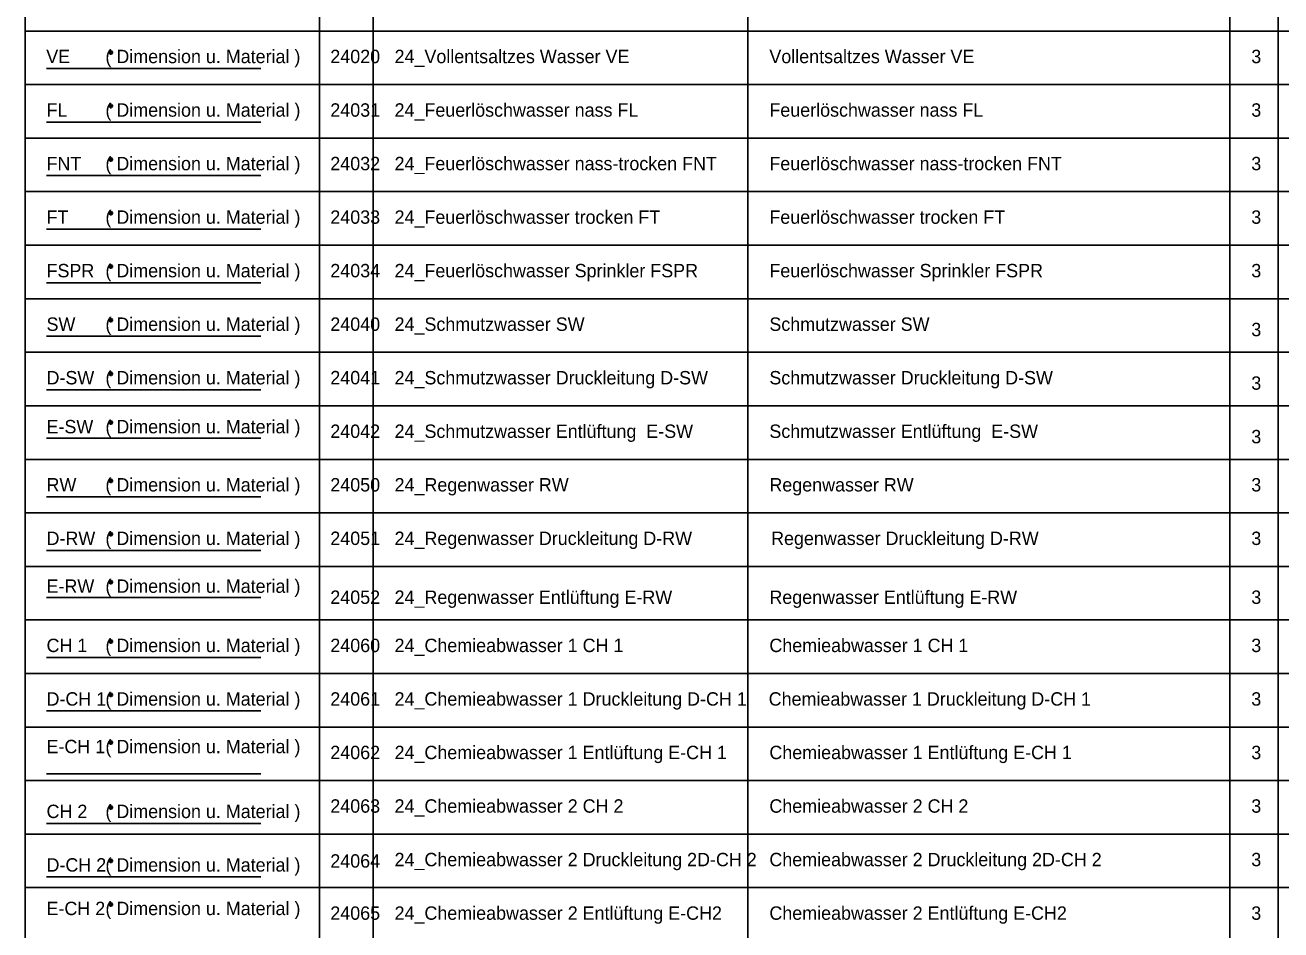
# Model space of a CAD drawing. Extents: x -29 to 48, y -113 to 16.
# Drawn here: x 0 to 23.45, y -30.79 to -13.89 of the extents above; entities that cross this region are included whole.
import ezdxf

# ---------------------------------------------------------------- set-up
doc = ezdxf.new("R2010")
doc.units = 0
for name, color, linetype in [('24_Chemieabwasser 1 CH 1', 7, 'Continuous'), ('24_Chemieabwasser 1 Druckleitung CH 1', 7, 'Continuous'), ('24_Chemieabwasser 1 Entlüftung E-CH 1', 7, 'Continuous'), ('24_Chemieabwasser 2 CH 2', 7, 'Continuous'), ('24_Chemieabwasser 2 Druckleitung CH 2', 7, 'Continuous'), ('24_Chemieabwasser 2 Entlüftung E-CH2', 7, 'Continuous'), ('24_Feuerlöschwasser nass FL', 7, 'Continuous'), ('24_Feuerlöschwasser nass-trocken FNT', 7, 'Continuous'), ('24_Feuerlöschwasser Sprinkler FSPR', 7, 'Continuous'), ('24_Feuerlöschwasser trocken FT', 7, 'Continuous'), ('24_Regenwasser Druckleitung D-RW', 7, 'Continuous'), ('24_Regenwasser Entlüftung E-RW', 7, 'Continuous'), ('24_Regenwasser RW', 7, 'Continuous'), ('24_Schmutzwasser Druckleitung D-SW', 7, 'Continuous'), ('24_Schmutzwasser Entlüftung  E-SW', 7, 'Continuous'), ('24_Schmutzwasser SW', 7, 'Continuous'), ('24_Vollentsaltzes Wasser VE', 7, 'Continuous'), ('Default', 7, 'Continuous')]:
    doc.layers.add(name, color=color, linetype=linetype)

msp = doc.modelspace()

# ---------------------------------------------------------------- linework, layer by layer
at = {"layer": '24_Chemieabwasser 1 CH 1'}
for p, q in [((1.556, -25.4), (1.644, -25.4)), ((1.569, -25.369), (1.631, -25.431)), ((1.631, -25.369), (1.569, -25.431)), ((1.6, -25.356), (1.6, -25.444)), ((0.4, -25.7), (4.4, -25.7))]:
    msp.add_line(p, q, dxfattribs=at)
at = {"layer": '24_Chemieabwasser 1 Druckleitung CH 1'}
for p, q in [((1.556, -26.4), (1.644, -26.4)), ((1.569, -26.369), (1.631, -26.431)), ((1.631, -26.369), (1.569, -26.431)), ((1.6, -26.356), (1.6, -26.444)), ((0.4, -26.7), (4.4, -26.7))]:
    msp.add_line(p, q, dxfattribs=at)
at = {"layer": '24_Chemieabwasser 1 Entlüftung E-CH 1'}
for p, q in [((1.556, -27.289), (1.644, -27.289)), ((1.569, -27.258), (1.631, -27.321)), ((1.631, -27.258), (1.569, -27.321)), ((1.6, -27.245), (1.6, -27.334)), ((0.4, -27.877), (4.4, -27.877))]:
    msp.add_line(p, q, dxfattribs=at)
at = {"layer": '24_Chemieabwasser 2 CH 2'}
for p, q in [((1.556, -28.5), (1.644, -28.5)), ((1.569, -28.469), (1.631, -28.531)), ((1.631, -28.469), (1.569, -28.531)), ((1.6, -28.456), (1.6, -28.544)), ((0.4, -28.8), (4.4, -28.8)), ((1.556, -29.5), (1.644, -29.5)), ((1.569, -29.469), (1.631, -29.531)), ((1.631, -29.469), (1.569, -29.531)), ((1.6, -29.456), (1.6, -29.544))]:
    msp.add_line(p, q, dxfattribs=at)
at = {"layer": '24_Chemieabwasser 2 Druckleitung CH 2'}
msp.add_line((0.4, -29.8), (4.4, -29.8), dxfattribs=at)
at = {"layer": '24_Chemieabwasser 2 Entlüftung E-CH2'}
for p, q in [((1.556, -30.313), (1.644, -30.313)), ((1.569, -30.282), (1.631, -30.344)), ((1.631, -30.282), (1.569, -30.344)), ((1.6, -30.269), (1.6, -30.357))]:
    msp.add_line(p, q, dxfattribs=at)
at = {"layer": '24_Feuerlöschwasser nass FL'}
for p, q in [((1.556, -15.4), (1.644, -15.4)), ((1.569, -15.369), (1.631, -15.431)), ((1.631, -15.369), (1.569, -15.431)), ((1.6, -15.356), (1.6, -15.444)), ((0.4, -15.7), (4.4, -15.7))]:
    msp.add_line(p, q, dxfattribs=at)
at = {"layer": '24_Feuerlöschwasser nass-trocken FNT'}
for p, q in [((1.556, -16.4), (1.644, -16.4)), ((1.569, -16.369), (1.631, -16.431)), ((1.631, -16.369), (1.569, -16.431)), ((1.6, -16.356), (1.6, -16.444)), ((0.4, -16.7), (4.4, -16.7))]:
    msp.add_line(p, q, dxfattribs=at)
at = {"layer": '24_Feuerlöschwasser Sprinkler FSPR'}
for p, q in [((1.556, -18.4), (1.644, -18.4)), ((1.569, -18.369), (1.631, -18.431)), ((1.631, -18.369), (1.569, -18.431)), ((1.6, -18.356), (1.6, -18.444)), ((0.4, -18.7), (4.4, -18.7))]:
    msp.add_line(p, q, dxfattribs=at)
at = {"layer": '24_Feuerlöschwasser trocken FT'}
for p, q in [((1.556, -17.4), (1.644, -17.4)), ((1.569, -17.369), (1.631, -17.431)), ((1.631, -17.369), (1.569, -17.431)), ((1.6, -17.356), (1.6, -17.444)), ((0.4, -17.7), (4.4, -17.7))]:
    msp.add_line(p, q, dxfattribs=at)
at = {"layer": '24_Regenwasser Druckleitung D-RW'}
msp.add_line((0.4, -23.7), (4.4, -23.7), dxfattribs=at)
at = {"layer": '24_Regenwasser Entlüftung E-RW'}
for p, q in [((1.556, -24.293), (1.644, -24.293)), ((1.569, -24.261), (1.631, -24.324)), ((1.631, -24.261), (1.569, -24.324)), ((1.6, -24.249), (1.6, -24.337)), ((0.4, -24.58), (4.4, -24.58))]:
    msp.add_line(p, q, dxfattribs=at)
at = {"layer": '24_Regenwasser RW'}
for p, q in [((1.556, -22.4), (1.644, -22.4)), ((1.569, -22.369), (1.631, -22.431)), ((1.631, -22.369), (1.569, -22.431)), ((1.6, -22.356), (1.6, -22.444)), ((0.4, -22.7), (4.4, -22.7)), ((1.556, -23.4), (1.644, -23.4)), ((1.569, -23.369), (1.631, -23.431)), ((1.631, -23.369), (1.569, -23.431)), ((1.6, -23.356), (1.6, -23.444))]:
    msp.add_line(p, q, dxfattribs=at)
at = {"layer": '24_Schmutzwasser Druckleitung D-SW'}
msp.add_line((0.4, -20.7), (4.4, -20.7), dxfattribs=at)
at = {"layer": '24_Schmutzwasser Entlüftung  E-SW'}
for p, q in [((1.556, -21.314), (1.644, -21.314)), ((1.569, -21.283), (1.631, -21.345)), ((1.631, -21.283), (1.569, -21.345)), ((1.6, -21.27), (1.6, -21.358)), ((0.4, -21.606), (4.4, -21.606))]:
    msp.add_line(p, q, dxfattribs=at)
at = {"layer": '24_Schmutzwasser SW'}
for p, q in [((1.556, -19.4), (1.644, -19.4)), ((1.569, -19.369), (1.631, -19.431)), ((1.631, -19.369), (1.569, -19.431)), ((1.6, -19.356), (1.6, -19.444)), ((0.4, -19.7), (4.4, -19.7)), ((1.556, -20.4), (1.644, -20.4)), ((1.569, -20.369), (1.631, -20.431)), ((1.631, -20.369), (1.569, -20.431)), ((1.6, -20.356), (1.6, -20.444))]:
    msp.add_line(p, q, dxfattribs=at)
at = {"layer": '24_Vollentsaltzes Wasser VE'}
for p, q in [((1.556, -14.4), (1.644, -14.4)), ((1.569, -14.369), (1.631, -14.431)), ((1.631, -14.369), (1.569, -14.431)), ((1.6, -14.356), (1.6, -14.444)), ((0.4, -14.7), (4.4, -14.7))]:
    msp.add_line(p, q, dxfattribs=at)
at = {"layer": 'Default'}
for p, q in [((0, 0), (0, -107)), ((5.5, 0), (5.5, -107)), ((6.5, 0), (6.5, -107)), ((13.5, 0), (13.5, -107)), ((22.5, 0), (22.5, -107)), ((23.4, -0.7), (23.4, -89)), ((0, -14), (32, -14)), ((0, -15), (32, -15)), ((0, -16), (32, -16)), ((0, -17), (32, -17)), ((0, -18), (32, -18)), ((0, -19), (32, -19)), ((0, -20), (32, -20)), ((0, -21), (32, -21)), ((0, -22), (32, -22)), ((0, -23), (32, -23)), ((0, -24), (32, -24)), ((0, -25), (32, -25)), ((0, -26), (32, -26)), ((0, -27), (32, -27)), ((0, -28), (32, -28)), ((0, -29), (32, -29)), ((0, -30), (32, -30))]:
    msp.add_line(p, q, dxfattribs=at)

# ---------------------------------------------------------------- texts
at = {"layer": '24_Chemieabwasser 1 CH 1'}
for s, p in [('CH 1', (0.4, -25.6)), ('( Dimension u. Material )', (1.5, -25.6))]:
    msp.add_text(s, height=0.25, dxfattribs=at).set_placement(p)
at = {"layer": '24_Chemieabwasser 1 Druckleitung CH 1'}
for s, p in [('D-CH 1', (0.4, -26.6)), ('( Dimension u. Material )', (1.5, -26.6))]:
    msp.add_text(s, height=0.25, dxfattribs=at).set_placement(p)
at = {"layer": '24_Chemieabwasser 1 Entlüftung E-CH 1'}
for s, p in [('E-CH 1', (0.4, -27.489)), ('( Dimension u. Material )', (1.5, -27.489))]:
    msp.add_text(s, height=0.25, dxfattribs=at).set_placement(p)
at = {"layer": '24_Chemieabwasser 2 CH 2'}
for s, p in [('CH 2', (0.4, -28.7)), ('( Dimension u. Material )', (1.5, -28.7))]:
    msp.add_text(s, height=0.25, dxfattribs=at).set_placement(p)
at = {"layer": '24_Chemieabwasser 2 Druckleitung CH 2'}
for s, p in [('D-CH 2', (0.4, -29.7)), ('( Dimension u. Material )', (1.5, -29.7))]:
    msp.add_text(s, height=0.25, dxfattribs=at).set_placement(p)
at = {"layer": '24_Chemieabwasser 2 Entlüftung E-CH2'}
for s, p in [('( Dimension u. Material )', (1.5, -30.513)), ('E-CH 2', (0.4, -30.513))]:
    msp.add_text(s, height=0.25, dxfattribs=at).set_placement(p)
at = {"layer": '24_Feuerlöschwasser nass FL'}
for s, p in [('FL', (0.4, -15.6)), ('( Dimension u. Material )', (1.5, -15.6))]:
    msp.add_text(s, height=0.25, dxfattribs=at).set_placement(p)
at = {"layer": '24_Feuerlöschwasser nass-trocken FNT'}
for s, p in [('FNT', (0.4, -16.6)), ('( Dimension u. Material )', (1.5, -16.6))]:
    msp.add_text(s, height=0.25, dxfattribs=at).set_placement(p)
at = {"layer": '24_Feuerlöschwasser Sprinkler FSPR'}
for s, p in [('FSPR', (0.4, -18.6)), ('( Dimension u. Material )', (1.5, -18.6))]:
    msp.add_text(s, height=0.25, dxfattribs=at).set_placement(p)
at = {"layer": '24_Feuerlöschwasser trocken FT'}
for s, p in [('FT', (0.4, -17.6)), ('( Dimension u. Material )', (1.5, -17.6))]:
    msp.add_text(s, height=0.25, dxfattribs=at).set_placement(p)
at = {"layer": '24_Regenwasser Druckleitung D-RW'}
for s, p in [('D-RW', (0.4, -23.6)), ('( Dimension u. Material )', (1.5, -23.6))]:
    msp.add_text(s, height=0.25, dxfattribs=at).set_placement(p)
at = {"layer": '24_Regenwasser Entlüftung E-RW'}
for s, p in [('E-RW', (0.4, -24.493)), ('( Dimension u. Material )', (1.5, -24.493))]:
    msp.add_text(s, height=0.25, dxfattribs=at).set_placement(p)
at = {"layer": '24_Regenwasser RW'}
for s, p in [('RW', (0.4, -22.6)), ('( Dimension u. Material )', (1.5, -22.6))]:
    msp.add_text(s, height=0.25, dxfattribs=at).set_placement(p)
at = {"layer": '24_Schmutzwasser Druckleitung D-SW'}
msp.add_text('( Dimension u. Material )', height=0.25, dxfattribs=at).set_placement((1.5, -20.6))
at = {"layer": '24_Schmutzwasser Entlüftung  E-SW'}
for s, p in [('E-SW', (0.4, -21.514)), ('( Dimension u. Material )', (1.5, -21.514))]:
    msp.add_text(s, height=0.25, dxfattribs=at).set_placement(p)
at = {"layer": '24_Schmutzwasser SW'}
for s, p in [('SW', (0.4, -19.6)), ('( Dimension u. Material )', (1.5, -19.6)), ('D-SW', (0.4, -20.6))]:
    msp.add_text(s, height=0.25, dxfattribs=at).set_placement(p)
at = {"layer": '24_Vollentsaltzes Wasser VE'}
for s, p in [('VE', (0.395, -14.6)), ('( Dimension u. Material )', (1.5, -14.6))]:
    msp.add_text(s, height=0.25, dxfattribs=at).set_placement(p)
at = {"layer": 'Default'}
for s, p in [('24020', (5.7, -14.6)), ('24_Vollentsaltzes Wasser VE', (6.9, -14.6)), ('Vollentsaltzes Wasser VE', (13.9, -14.6)), ('3', (22.9, -14.6)), ('24031', (5.7, -15.6)), ('24_Feuerlöschwasser nass FL', (6.9, -15.6)), ('Feuerlöschwasser nass FL', (13.9, -15.6)), ('3', (22.9, -15.6)), ('24032', (5.7, -16.6)), ('24_Feuerlöschwasser nass-trocken FNT', (6.9, -16.6)), ('Feuerlöschwasser nass-trocken FNT', (13.9, -16.6)), ('3', (22.9, -16.6)), ('24033', (5.7, -17.6)), ('24_Feuerlöschwasser trocken FT', (6.9, -17.6)), ('Feuerlöschwasser trocken FT', (13.9, -17.6)), ('3', (22.9, -17.6)), ('24034', (5.7, -18.6)), ('24_Feuerlöschwasser Sprinkler FSPR', (6.9, -18.6)), ('Feuerlöschwasser Sprinkler FSPR', (13.9, -18.6)), ('3', (22.9, -18.6)), ('24040', (5.7, -19.6)), ('24_Schmutzwasser SW', (6.9, -19.6)), ('Schmutzwasser SW', (13.9, -19.6)), ('3', (22.9, -19.7)), ('24041', (5.7, -20.599)), ('24_Schmutzwasser Druckleitung D-SW', (6.9, -20.6)), ('Schmutzwasser Druckleitung D-SW', (13.9, -20.6)), ('3', (22.9, -20.7)), ('24_Schmutzwasser Entlüftung  E-SW', (6.9, -21.6)), ('Schmutzwasser Entlüftung  E-SW', (13.9, -21.6)), ('24042', (5.7, -21.6)), ('3', (22.9, -21.7)), ('24050', (5.7, -22.6)), ('24_Regenwasser RW', (6.9, -22.6)), ('Regenwasser RW', (13.9, -22.6)), ('3', (22.9, -22.6)), ('24051', (5.7, -23.6)), ('24_Regenwasser Druckleitung D-RW', (6.9, -23.6)), ('Regenwasser Druckleitung D-RW', (13.932, -23.6)), ('3', (22.9, -23.6)), ('24052', (5.7, -24.7)), ('24_Regenwasser Entlüftung E-RW', (6.9, -24.7)), ('Regenwasser Entlüftung E-RW', (13.9, -24.7)), ('3', (22.9, -24.7)), ('24060', (5.7, -25.6)), ('24_Chemieabwasser 1 CH 1', (6.9, -25.6)), ('Chemieabwasser 1 CH 1', (13.9, -25.6)), ('3', (22.9, -25.6)), ('24061', (5.7, -26.6)), ('24_Chemieabwasser 1 Druckleitung D-CH 1', (6.9, -26.6)), ('Chemieabwasser 1 Druckleitung D-CH 1', (13.887, -26.6)), ('3', (22.9, -26.6)), ('24062', (5.7, -27.6)), ('24_Chemieabwasser 1 Entlüftung E-CH 1', (6.9, -27.6)), ('Chemieabwasser 1 Entlüftung E-CH 1', (13.9, -27.6)), ('3', (22.9, -27.6)), ('24063', (5.7, -28.6)), ('24_Chemieabwasser 2 CH 2', (6.9, -28.6)), ('Chemieabwasser 2 CH 2', (13.9, -28.6)), ('3', (22.9, -28.6)), ('24064', (5.7, -29.626)), ('24_Chemieabwasser 2 Druckleitung 2D-CH 2', (6.9, -29.6)), ('Chemieabwasser 2 Druckleitung 2D-CH 2', (13.9, -29.6)), ('3', (22.9, -29.6)), ('24065', (5.7, -30.6)), ('24_Chemieabwasser 2 Entlüftung E-CH2', (6.9, -30.6)), ('Chemieabwasser 2 Entlüftung E-CH2', (13.9, -30.6)), ('3', (22.9, -30.6))]:
    msp.add_text(s, height=0.25, dxfattribs=at).set_placement(p)

doc.saveas('drawing.dxf')
